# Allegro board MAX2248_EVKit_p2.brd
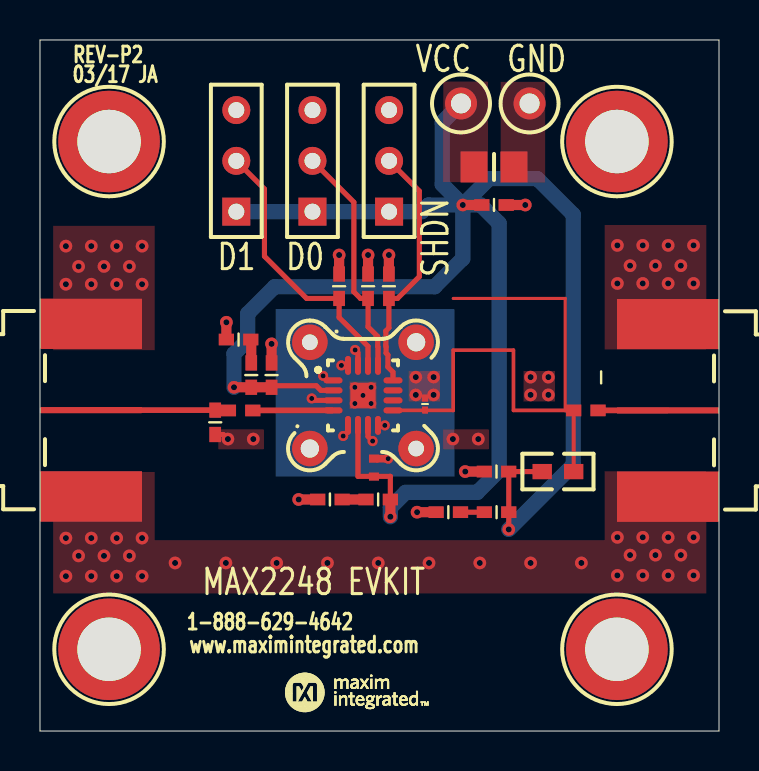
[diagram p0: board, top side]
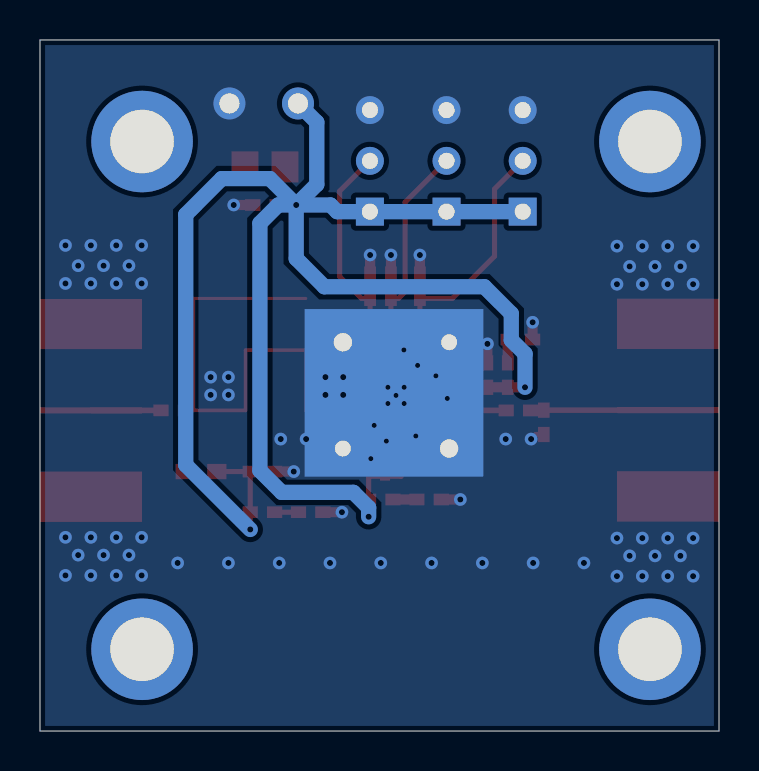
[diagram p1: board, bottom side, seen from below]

Outline 33.96 x 34.57 mm; copper layers: TOP, L2_GND, L3_PWR, BOTTOM. Coordinates in mm from the lower left corner of the outline.
Outline path: 0,34.57 0,0 33.96,0 33.96,34.57 0,34.57

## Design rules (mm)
constraint set DEFAULT: min track width 0.254

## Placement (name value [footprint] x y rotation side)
C1  1UF  [CAPC2012X140M]  22.71 28.22 180 top
C2  0.01UF  [0402]  22.71 26.31 180 top
C3  470PF  [0402]  14.96 22.25 270 top
C4  1000PF  [0402]  10.57 17.81 270 top
C5  220PF  [0402]  11.58 17.81 270 top
C6  470PF  [0402]  16.41 22.25 90 top
C7  470PF  [0402]  17.45 22.25 270 top
C8  18PF  [0402#2]  16.7 13.18 270 top
C9  1000PF  [0402]  16.91 11.58 0 top
C10  8PF  [0402]  27.3 16.04 0 top
C11  220PF  [0402]  22.83 12.98 0 top
C12  1000PF  [0402]  22.83 10.95 180 top
C13  1PF  [0402]  8.76 15.44 90 top
C14  0.1UF  [CAPC0603X23L]  19.26 16.36 270 top
J1  142-0701-851  [JOHNSON_142-0701-851]  -5.55 16.05 270 top
J2  HEADER_3P  [HDR_3P]  9.82 25.98 90 top
J3  HEADER_3P  [HDR_3P]  13.63 25.98 90 top
J4  HEADER_3P  [HDR_3P]  17.46 25.98 90 top
J5  142-0701-851  [JOHNSON_142-0701-851]  39.51 16.04 90 top
L1  22NH  [0603]  25.9 12.98 180 top
L2  1.5NH  [0402]  10.03 16.04 0 top
NOREF  -  [unnamed]  28.85 4.09 0 top
NOREF#2  -  [#2]  0 0 0 top
NOREF#3  -  [#2]  0 0 90 top
NOREF#4  -  [#2]  134.9 -14.96 0 top
NOREF#5  -  [unnamed]  3.45 29.49 0 top
NOREF#6  -  [#2]  13.23 1.93 0 top
NOREF#7  -  [unnamed]  3.45 4.09 0 top
NOREF#8  -  [#2]  25.68 85.37 0 top
NOREF#9  -  [unnamed#3]  16.15 16.79 180 top
NOREF#10  -  [unnamed]  28.85 29.49 0 top
R1  8.2  [0402]  9.93 19.58 0 top
R2  8.2  [0402]  14.5 11.58 0 top
R3  8.2  [0402]  20.42 10.95 0 top
SU2  STC02SYAN  [EVKIT_SHUNT]  37.19 -4.06 0 top
SU3  STC02SYAN  [EVKIT_SHUNT]  49.76 -3.91 0 top
SU4  STC02SYAN  [EVKIT_SHUNT]  43.84 -11.99 0 top
TP1  N/A  [TP_180P120D460H]  21.06 31.39 0 top
TP2  N/A  [TP_180P120D460H]  24.49 31.39 0 top
U1  WR98  [QFN50P300X300X80-17M]  16.15 16.79 0 top

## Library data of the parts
C1 = CAP_NP: alternate symbols: CAPC2012X145L; part number: CAP_NP_0805CAP-CAPC2012X140M,1UF,20-0001U-11A
C2 = CAP_NP: alternate symbols: 0402_NOSILK,CAPC1005X50L; part number: CAP_NP_0402CAP-0402,0.01UF,20-00U01-12
C3 C6 C7 = CAP_NP: alternate symbols: (0402_NOSILK); part number: CAP_NP_0402CAP-0402,470PF,20-0470P-27
C4 C9 C12 = CAP_NP: alternate symbols: 0402_NOSILK,CAPC1005X50L; part number: CAP_NP_0402CAP-0402,1000PF,20-1000P-27
C5 C11 = CAP_NP: alternate symbols: 0402_NOSILK,CAPC1005X50L; part number: CAP_NP_0402CAP-0402,220PF,20-0220P-BA31
C8 = CAP_NP: alternate symbols: 0402_NOSILK,CAPC1005X50L; part number: CAP_NP_0402CAP-0402,18PF,20-0018P-27
C10 = CAP_NP: alternate symbols: (0402_NOSILK); part number: CAP_NP_0402CAP-0402,8PF,20-0008P-E1
C13 = CAP_NP: alternate symbols: (0402_NOSILK); part number: CAP_NP_0402CAP-0402,1PF,20-0001P-N7A
C14 = EK_CAP_NP: part number: EK_CAP_NP_0201_FF-CAPC0603X23L,0.1UF,20-000U1-A48
J1 J5 = 142-0701-851: alternate symbols: JOHNSON_142-0701-851_ALT_PIN1_20MILS;JOHNSON_142-0701-851_ALT_PIN1_12MILS; part number: 142-0701-851_TMD-JOHNSON_142-0701-851,142-0701-851,01-14207018512P-01
J2-J4 = HEADER_3P: part number: HEADER_3P_SIP-HDR_3P,HEADER_3P,01-80010003100010003P-21
L1 = INDUCT: alternate symbols: 0603_NOSILK,INDC1608X90L; part number: INDUCT_0603-0603,22NH,50-0022N-0NU
L2 = INDUCT: alternate symbols: (0402_NOSILK); part number: INDUCT_0402-0402,1.5NH,50-001N5-0BQ
R1-R3 = RES: alternate symbols: 0402_NOSILK,RESC1005X50L; part number: RES_0402RES-0402,8.2,80-008R2-BA29
SU2-SU4 = SHUNT: part number: SHUNT_SHUNT_2P-02-JMPFSTC02SYAN-00,STC02SYAN,EVKIT_SHUNT
TP1 = TP: part number: TP_TP-TP_180P120D460H,N/A,02-TPMINI5000-00
TP2 = TP: part number: TP_TP-TP_180P120D460H,N/A,02-TPMINI5001-00
U1 = EK_WR98: part number: EK_WR98_TQFN16-EP-QFN50P300X300X80-17M,WR98,N/A

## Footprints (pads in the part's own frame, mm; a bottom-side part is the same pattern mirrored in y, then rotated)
0402
  rect 0.762x0.584 smd: 1(-0.61,0) 2(0.61,0)
0402#2
  rect 0.4x0.5 smd: 1(-0.45,0) 2(0.45,0)
0603
  rect 0.965x0.762 smd: 1(-0.787,0) 2(0.787,0)
CAPC0603X23L
  rect 0.35x0.3 smd: 1(-0.3,0) 2(0.3,0)
CAPC2012X140M
  rect 1.35x1.55 smd: 1(-1,0) 2(1,0)
HDR_3P
  rect 1.4x1.4 hole 0.8: 1(0,0)
  round 1.4 hole 0.8: 2(2.54,0) 3(5.08,0)
JOHNSON_142-0701-851
  rect 0.305x5.1 smd: 1(0,8.1)
  rect 2.5x5.1 smd: 2(4.318,8.1) 3(-4.318,8.1) 4(-4.318,8.1) 5(4.318,8.1)
QFN50P300X300X80-17M
  oval 0.95x0.3 smd: 1(-1.5,0.75) 2(-1.5,0.25) 3(-1.5,-0.25) 4(-1.5,-0.75) 9(1.5,-0.75) 10(1.5,-0.25) 11(1.5,0.25) 12(1.5,0.75)
  oval 0.3x0.95 smd: 5(-0.75,-1.5) 6(-0.25,-1.5) 7(0.25,-1.5) 8(0.75,-1.5) 13(0.75,1.5) 14(0.25,1.5) 15(-0.25,1.5) 16(-0.75,1.5)
  rect 1.25x1.25 smd: 17(0,0)
TP_180P120D460H
  round 1.6 hole 1: 1(0,0)
unnamed
  round 5.08 hole 3.175: (0,0)
unnamed#3
  round 1.778 hole 0.787: (-2.658,2.658) (2.658,-2.658)
  round 1.778 hole 0.914: (-2.658,-2.658) (2.658,2.658)

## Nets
GND_POWER: C1.1 C2.1 C3.1 C5.1 C6.2 C7.1 C8.1 C11.1 C13.1 C14.1 J1.2 J1.3 J1.4 J1.5 J2.3 J3.3 J4.3 J5.2 J5.3 J5.4 J5.5 R1.1 R2.1 R3.1 TP2.1(TP1) U1.1 U1.3 U1.5 U1.7 U1.8 U1.15 U1.16 U1.17(EP)
VCC: C1.2 C2.2 C4.2 C5.2 C8.2 C9.2 C11.2 C12.1 J2.1 J3.1 J4.1 L1.2 TP1.1(TP1) U1.2 U1.6
UNNAMED_1_142-0701-851_I57_1: C13.2 J1.1 L2.1
UNNAMED_1_142-0701-851_I58_1: C10.2 J5.1
UNNAMED_1_CAPNP_I1_1: C6.1 J3.2 U1.13
UNNAMED_1_CAPNP_I2_2: C3.2 J2.2 U1.14
UNNAMED_1_CAPNP_I7_1: C10.1 C14.2 L1.1 U1.9
UNNAMED_1_CAPNP_I8_1: C9.1 R2.2
UNNAMED_1_CAPNP_I9_2: C12.2 R3.2
UNNAMED_1_CAPNP_I10_1: C4.1 R1.2
UNNAMED_1_EKWR98_I37_4: L2.2 U1.4
UNNAMED_1_HEADER3P_I13_2: C7.2 J4.2 U1.12

Pads without a net: U1 10 11

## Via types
v1: diameter 0.635, hole 0.305, TOP to BOTTOM, 78 vias
v2: diameter 0.508, hole 0.254, TOP to BOTTOM, 13 vias

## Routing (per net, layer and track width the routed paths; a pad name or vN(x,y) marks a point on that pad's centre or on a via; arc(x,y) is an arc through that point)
GND_POWER: length 14.7
  TOP w0.254: v2(15.76,19.06) 15.9,18.92 U1.15 ; v2(13.59,16.64) 13.69,16.54 U1.3 ; v1(9.4,14.61) 9.17,14.83 C13.1 ; 19.23,16.69 19.26,16.66 C14.1 ; C8.1 16.8,13.63 16.8,13.63 ; U1.5 15.4,15 v2(15.16,14.76) ; v2(16.64,14.5) 16.4,14.74 U1.7 ; U1.1 14.39,17.54 v2(14.16,17.77) ; U1.16 v2(15.07,18.29) ; U1.8 v2(17.25,15.29)
  TOP w0.381: 16.8,13.63 v2(17.41,13.63)
  TOP w0.508: R3.1 v1(18.86,10.95) ; C2.1 v1(24.27,26.31) ; R1.1 v1(9.32,20.45) ; C11.1 v1(21.27,12.98) ; C6.2 v1(16.41,23.81) ; R2.1 v1(12.94,11.58) ; C3.1 v1(14.96,23.81) ; C7.1 v1(17.45,23.81) ; C5.1 v1(11.58,19.37)
  vias: v1(1.3,24.26) v1(1.3,22.35) v1(1.3,9.65) v1(1.3,7.75) v1(1.93,23.24) v1(1.93,8.76) v1(2.57,24.26) v1(2.57,22.35) v1(2.57,9.65) v1(2.57,7.75) v1(3.2,23.24) v1(3.2,8.76) v1(3.84,24.26) v1(3.84,22.35) v1(3.84,9.65) v1(3.84,7.75) v1(4.47,23.24) v1(4.47,8.76) v1(5.11,24.26) v1(5.11,22.35) v1(5.11,9.65) v1(5.11,7.75) v1(6.76,8.41) v1(9.3,8.41) v1(10.67,14.61) v1(11.84,8.41) v1(14.38,8.41) v1(16.92,8.41) v1(18.8,17.7) v1(18.8,16.81) v1(19.46,8.41) v1(19.69,17.7) v1(19.69,16.81) v1(20.65,14.61) v1(21.92,14.61) v1(22,8.41) v1(24.54,17.7) v1(24.54,16.81) v1(24.54,8.41) v1(25.43,17.7) v1(25.43,16.81) v1(27.08,8.41) v1(28.88,24.29) v1(28.88,22.39) v1(28.88,9.69) v1(28.88,7.78) v1(29.51,23.28) v1(29.51,8.8) v1(30.15,24.29) v1(30.15,22.39) v1(30.15,9.69) v1(30.15,7.78) v1(30.78,23.28) v1(30.78,8.8) v1(31.42,24.29) v1(31.42,22.39) v1(31.42,9.69) v1(31.42,7.78) v1(32.05,23.28) v1(32.05,8.8) v1(32.69,24.29) v1(32.69,22.39) v1(32.69,9.69) v1(32.69,7.78) v2(15.75,17.2) v2(15.75,16.38) v2(16.15,16.79) v2(16.56,17.2) v2(16.56,16.38)
VCC: length 97.9
  TOP w0.254: 23.44,12.98 C12.1 v1(23.44,10.08) ; 23.44,12.98 C11.2 ; 23.44,12.98 L1.2 ; C9.2 17.52,12.74 16.74,12.74 ; C5.2 11.66,17.27 13.82,17.27 14.05,17.04 U1.2 ; 16.74,12.74 16.73,12.73 C8.2 ; 16.74,12.74 15.9,12.74 U1.6
  TOP w0.508: C9.2 v1(17.52,10.72) ; C5.2 C4.2 v1(9.7,17.2) ; C2.2 v1(21.15,26.31)
  BOTTOM w0.762: TP1.1 20.12,30.45 20.12,27.34 v1(21.15,26.31) ; v1(21.15,26.31) 21.15,23.63 19.74,22.23 11.73,22.23 10.39,20.88 10.39,19.56 9.7,18.87 v1(9.7,17.2) ; v1(21.15,26.31) 22.05,26.31 22.96,25.4 22.96,13.03 21.87,11.94 18.28,11.94 17.52,11.18 v1(17.52,10.72) ; v1(21.15,26.31) 22.47,27.64 24.87,27.64 26.67,25.83 26.67,13.31 v1(23.44,10.08) ; v1(21.15,26.31) 19.43,26.31 19.1,25.98 J4.1 J3.1 J2.1
UNNAMED_1_142-0701-851_I57_1: length 7.4
  TOP w0.254: 8.95,16.05 8.97,16.04 L2.1
  TOP w0.279: L2.1 9.41,16.05 C13.2 J1.1
UNNAMED_1_142-0701-851_I58_1: length 3.5
  TOP w0.279: J5.1 C10.2
UNNAMED_1_CAPNP_I1_1: length 11.8
  TOP w0.254: J3.2 15.7,26.45 15.7,21.97 16.03,21.64 C6.1 16.41,20.22 16.89,19.74 16.89,19.26 16.9,19.18 U1.13
UNNAMED_1_CAPNP_I2_2: length 13.9
  TOP w0.254: U1.14 16.4,19.25 14.96,20.69 C3.2 13.34,21.64 11.23,23.75 11.23,27.11 J2.2
UNNAMED_1_CAPNP_I7_1: length 29.4
  TOP w0.152: 26.27,16.04 26.27,21.64 20.67,21.64
  TOP w0.178: U1.9 20.67,16.04 20.67,19.05 23.68,19.05 23.68,16.04 26.27,16.04
  TOP w0.191: L1.1 C10.1 26.27,16.04
  TOP w0.254: C14.2 19.25,16.06 19.23,16.04
UNNAMED_1_CAPNP_I8_1: length 1.2
  TOP w0.508: C9.1 R2.2
UNNAMED_1_CAPNP_I9_2: length 1.2
  TOP w0.254: C12.2 R3.2
UNNAMED_1_CAPNP_I10_1: length 1.2
  TOP w0.508: R1.2 10.57,19.56 C4.1
UNNAMED_1_EKWR98_I37_4: length 4
  TOP w0.279: U1.4 10.65,16.04 L2.2
UNNAMED_1_HEADER3P_I13_2: length 12.7
  TOP w0.254: U1.12 17.65,17.96 17.4,18.21 17.4,18.82 17.31,18.91 17.31,19.22 17.3,19.3 17.3,20.01 17.45,20.17 C7.2 17.88,21.64 18.97,22.73 18.97,27.01 J4.2

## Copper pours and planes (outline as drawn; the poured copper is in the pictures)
GND_POWER on BOTTOM (solid shape): 20.73,12.73 11.81,12.73 11.79,12.75 11.79,21.11 20.73,21.11
GND_POWER on L2_GND (solid shape): 20.73,12.37 11.79,12.37 11.79,21.11 20.73,21.11
GND_POWER on L3_PWR (solid shape): 20.47,12.52 11.91,12.52 11.91,21.08 20.47,21.08
GND_POWER on TOP: 25.76,18.01 25.76,16.48 24.18,16.48 24.18,18.01
GND_POWER on TOP: 11.2,15.09 11.2,14.1 8.92,14.1 8.92,15.09
GND_POWER on TOP: 5.74,25.27 5.74,19.05 0.66,19.05 0.66,25.27
GND_POWER on TOP: 20.02,18.01 20.02,16.48 18.44,16.48 18.44,18.01
GND_POWER on TOP: 0.66,6.88 0.66,12.95 5.74,12.95 5.74,9.55 28.24,9.55 28.24,12.99 33.32,12.99 33.32,6.88
GND_POWER on TOP: 23.03,32.47 25.27,32.47 25.27,27.44 23.03,27.44
GND_POWER on TOP: 16.84,16.1 16.84,17.48 15.47,17.48 15.47,16.1
GND_POWER on TOP: 22.45,15.09 22.45,14.1 20.17,14.1 20.17,15.09
GND_POWER on TOP: 33.32,25.31 33.32,19.09 28.24,19.09 28.24,25.31
GND_POWER on BOTTOM, L2_GND, L3_PWR: 0.26,0.26 0.26,34.31 33.7,34.31 33.7,0.26
VCC on TOP: 22.4,27.46 20.17,27.46 20.17,32.49 22.4,32.49

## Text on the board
Ref Des/Silkscreen Top: 03/17 JA | REV-P2 | 1-888-629-4642 | www.maximintegrated.com | MAX2248 EVKIT | D1 | D0 | VCC | GND | SHDN
FAB_NOTES: NOTES: | FINISH: | TESTING: | MISCELLANEOUS: | TOOLING: | 16.  VENDOR LOGO & DATE CODE REQUIRED IN INK ON BOTTOM SIDE ONLY. DATE CODE FORMAT MUST BE YYWW ONLY | 17.  FINAL ELECTRICAL TEST TO BE PERFORMED USING PROVIDED IPC-D-356A NETLIST OR ODB++ FORMAT FILE. | 18.  A TIME DOMAIN REFLECTOMETER REPORT FOR EACH IMPEDANCE CONTROLLED LAYER AND A CERTIFICATE | 15.  CHECK ALL THAT APPLY | 14.  CHECK ALL THAT APPLY | 19. IF PRESENT, ALL BLIND/BURIED VIAS WITH AN ASPECT RATIO <1:1 TO BE PLATED SHUT WITH COPPER WHEN | 20.  FOR ALL DRILL INFORMATION REFER TO DRILL CHART. | 21.  FINISHED SURFACE CONTACTS AND FILLED VIAS TO BE FREE OF ANY PITS. SCRATCHES PROBE MARKS | 23.  PEMNUT | 13.  DRILL SIZES ARE FINISHED HOLE SIZES. ALL HOLES SHALL BE LOCATED WITHIN .005 DTP. | 22.  THIEVING: | 9.  ALL TRACES FILLETED OPTION TO ENHANCE RELIABILITY AT PAD JUNCTIONS | 10.  LAYER TO LAYER REGISTRATIONS SHALL BE WITHIN .003 INCHES. | MATERIAL: | 11.  FINISHED COPPER WEIGHT/THICKNESS: | 12.  CHECK ALL THAT APPLY | 8.  IF STATED IN THE LAMINATION DIAGRAM, THE DIELECTRIC THICKNESS OF ANY | 1.  DIMENSIONS ARE IN INCHES (EXCEPT WHERE NOTED). | 3.  THE PCB SHALL BE FABRICATED TO IPC-6012, TYPE X, CLASS 2. | 4.  BOARD MATERIAL & CONSTRUCTION SHALL MEET THE REQUIREMENTS OF UL796 | 5.  OVERALL BOARD THICKNESS REFER TO LAMINATION DIAGRAM. TOLERANCE APPLIES | 6.  BOW & TWIST NOT TO EXCEED 0.0075 IN. (0.75%) PER LINEAR INCH. | 7.  PHOTO ETCH CIRCUITRY PER ENCLOSED GERBER RS274X OR ODB++ FORMAT FILE. | 2.  BOARD MATERIAL: | ( )  FINISH CONDUCTOR SURFACES: IMMERSION GOLD, 2-5 MICRO INCHES OVER | (X)  REFER TO LAMINATION DIAGRAM FOR FINISHED COPPER WEIGHT/THICKNESS REQUIREMENTS. | ( )  OTHER ________________________ | (X)  FINISH CONDUCTOR SURFACES: IMMERSION GOLD, 3-8 MICRO INCHES OVER | ( )  FINGERS TO BE GOLD PLATED. | ( )  LEAD FREE AND RoHS COMPLIANT PLATING. | (X)  GREEN SOLDERMASK OVER BARE COPPER/BARE GOLD (BOTH SIDES) WITH LIQUID PHOTO IMAGEABLE INK (LPI) | ( )  GREEN TAIYO PSR-4000 | ( )  ELECTRODEPOSITED HARD GOLD PLATE, TYPE 1 (99.7% MIN GOLD), GRADE C | (X)  APPLY SILKSCREEN USING A NON-CONDUCTIVE, WHITE EPOXY | MINIMUM BARREL PLATING OF .001 IN. PLATED HOLES SHALL NOT BE ROUGH OR IRREGULAR | SO AS TO HINDER PROPER SOLDER WICKING. | USED AS VIA-IN PAD OR AS A STACKED VIA. BLIND/BURIED VIAS WITH AN ASPECT RATIO >1:1 TO BE FILLED | WITH NON-CONDUCTIVE EPOXY. UNLESS OTHERWISE SPECIFIED. | ( )  NON-CONDUCTIVE EPOXY. FILL AND CAP ALL 0.XXXX INCH DRILLED VIAS. | ( )  SILVER. FILL AND CAP ALL 0.XXXX INCH DRILLED VIAS. | (REQUIRED UNLESS OTHERWISE SPECIFIED IN QUOTE) | THE PCB SHALL HAVE A VERIFICATION STAMP. | OR OTHER DEFORMITIES THAT COULD EFFECT THE APPERANCE AND PERFORMACE OF THE CONTACT | SURFACE. CONTACTS ARE TO BE AS FLAT AS POSSIBLE. NOT TO EXCEED +/- 0.001" OF FLATNESS. | OF COMPLIANCE SHALL BE PROVIDED BY VENDOR AT TIME OF SHIPMENT. INSTANCES WHERE TDR TESTING | CAN'T BE PERFORMED BECAUSE THE TRACE LENGTH IS TOO SHORT ON THE OUTER LAYERS AT THE PIN ESCAPES | IS ACCEPTABLE, ALL OTHER INSTANCES MUST BE REPORTED. | ( )  SUPPLIER MAY ADD THIEVING TO COMPENSATE FOR LOW COPPER DENSITY AREAS ON THIS DESIGN. | WHERE SPACING PERMITS. | LEGEND TO LEGEND +/- 0.007 INCHES | (X)  SUPPLIER MAY NOT ADD THIEVING TO COMPENSATE FOR LOW COPPER DENSITY AREAS ON THIS DESIGN. | ( )  PEMNUTS TO BE INSTALLED BY SUPPLIER. | ( )  PEMNUTS NOT TO BE INSTALLED BY SUPPLIER. | (X)  NOT APPLICABLE | CONTROLLED IMPEDANCE LAYER IS FOR REFERENCE ONLY. FINAL ACCEPTANCE | SHALL BE DETERMINED BY THESE LAYERS HAVING A CHARACTERISTIC | IMPEDANCE OF +/-10% OHMS AS STATED IN THE LAMINATION DIAGRAM. THE | VENDOR CAN MAKE ADJUSTMENTS AS LONG AS THE STATED IMPEDANCE AND | OVERALL BOARD THICKNESS IS MAINTAINED. ANY ADJUSTMENT MADE TO TRACE | WIDTH OR SPACING MUST HAVE PRIOR WRITTEN APPROVAL FROM MAXIM. | ( )  FILLETED | (X)  NOT FILLETED | ( )  ISOLA 370HR OR EQUIVALENT | ( )  NELCO-4000-13 | ( )  MEGTRON 6 | ( )  ROGERS 4350B | ( )  ROGERS 4003C | (X)  ISOLA-FR408HR OR EQUIVALENT | WORKMANSHIP SHALL CONFORM TO IPC-A-600, CLASS 2, CURRENT REVISIONS. | WITH FLAMMABILITY RATING OF 94V-O. | AFTER ALL LAMINATION AND PLATING PROCESSES. IT IS TO BE MEASURED FROM | TOP PCB METAL TO BOTTOM PCB METAL UNLESS OTHERWISE SPECIFIED. | BOW & TWIST SHOULD BE MEASURED PER IPC-TM-650, METHOD 2.4.22. | DRILL LOCATION AND SIZE CONTROLLED BY EXCELLON CNC DRILL FILE. | UNLESS OTHERWISE SPECIFIED | THE STARTING COPPER WEIGHT/THICKNESS CAN VARY AS LONG AS THE FINISHED COPPER | WEIGHT/THICKNESS IS NOT LESS THAN THE SPECIFIED VALUE. UNLESS OTHERWISE SPECIFIED. | (KNOOP HARDNESS 130-200), CLASS 1 (50-100 MICRO INCHES THICK) IN ACCORDANCE WITH MIL-G-45204C. | GENERAL SURFACING REQUIREMENTS MUST MEET ANSI/IPC-A-600(CURRENT REV) SECTION 4.0, | CLASS 3 (50-100 MICROINCHES THICK) OVER ELECTRODEPOSITED NICKEL PLATE | IN ACCORDANCE WITH ANSI/IPC-A-600D, SECTION 4.0, CLASS 3 (200-600 MICROINCHES THICK). | 100 MICRO INCHES MINIMUM OF ELECTROLESS NICKEL. | 118-236 MICRO INCHES MINIMUM OF ELECTROLESS NICKEL. | PER ARTWORK. | BASED INK PER ARTWORK. | (USE CHECKED ITEMS FOR MATERIAL) | (USE CHECKED ITEMS FOR PLATING) | (USE CHECKED ITEMS FOR TOOLING) | UNLESS OTHERWISE SPECIFIED: | JOANNA ALIM | 11/19/2016 | P1 | INITIAL RELEASE | JA | 11/19/16 | MAX2248_EVKIT_P2
User.25: FIGURE | SIZE | 10.0 | 12.0 | 30.98 | 31.5 | 35.98 | 39.37 | 125.0 | TOLERANCE | +3.0/-8.0 | +3.0/-10.0 | +2.0/-2.0 | +3.0/-3.0 | PLATED | ALL UNITS ARE IN MILS | QTY | 13 | 78 | 2 | 9 | 4 | NOTES | DRILL CHART: TOP to BOTTOM
